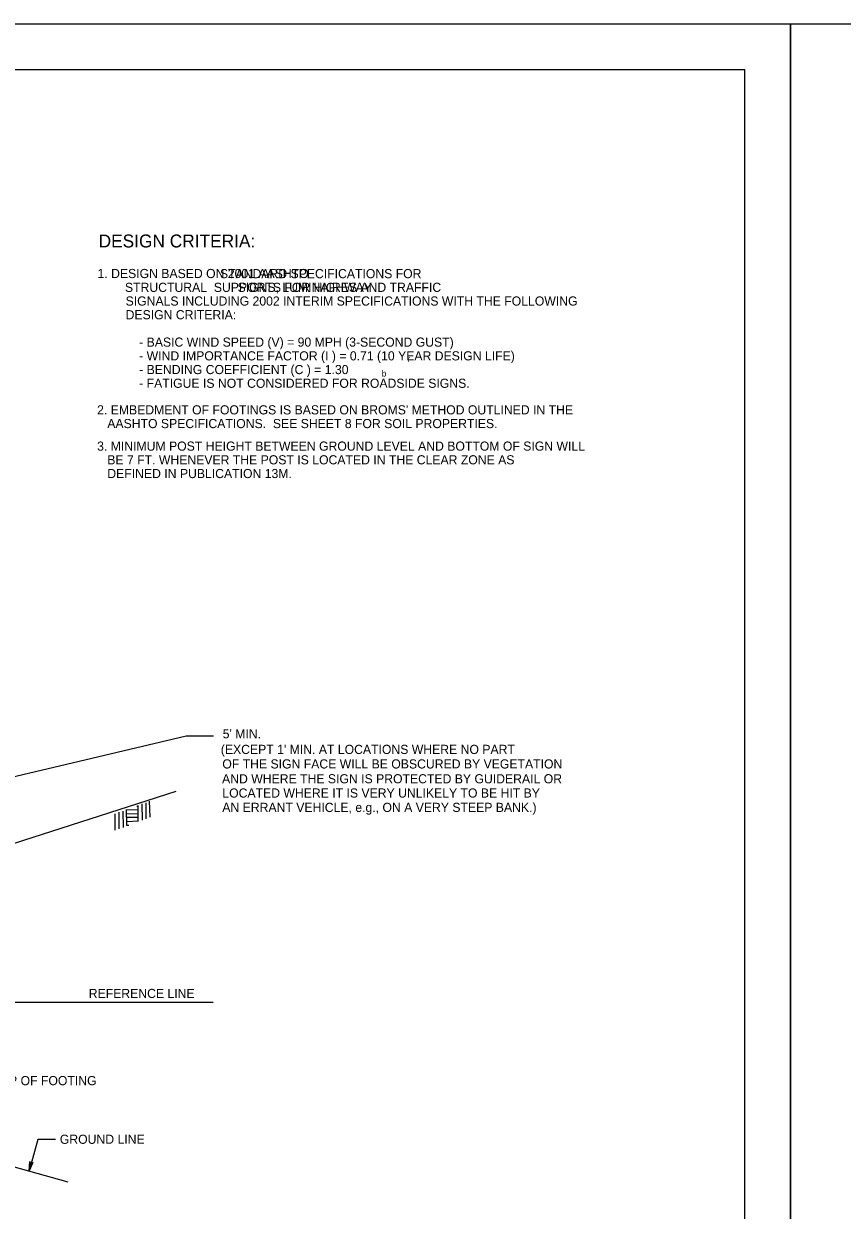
# Model space of a CAD drawing. Extents: x 637580 to 641008, y 294594 to 295782.
# Drawn here: x 638169.4 to 638438.3, y 295392.1 to 295781.6 of the extents above; entities that cross this region are included whole.
import ezdxf

# ---------------------------------------------------------------- set-up
doc = ezdxf.new("R2010")
doc.units = 0
for name, color, linetype in [('1', 7, 'Continuous'), ('2', 7, 'Continuous'), ('3', 7, 'Continuous'), ('PLT-BNDY', 7, 'Continuous')]:
    doc.layers.add(name, color=color, linetype=linetype)

# ---------------------------------------------------------------- blocks, each defined once
blk = doc.blocks.new('RARROW')
at = {"layer": '3'}
blk.add_lwpolyline([(-2.2695, 0.285), (-2.184875, 0.12075), (0, 0), (-2.2695, 0.285), (-2.38575, 0.384625), (0, 0), (-2.183125, -0.108), (-2.262875, -0.2705), (0, 0), (-2.38575, -0.379125), (-2.262875, -0.2705)], dxfattribs=at)

msp = doc.modelspace()

# ---------------------------------------------------------------- linework, layer by layer
at = {"layer": '1'}
for p, q in [((637620.31, 295766.63), (638406.31, 295766.63)), ((638406.31, 295202.63), (638406.31, 295766.63)), ((638148.69, 295530.25), (638222.81, 295547.88)), ((638210.94, 295521.13), (638210.81, 295526.38)), ((638199.44, 295516.88), (638199.44, 295522.25)), ((638200.81, 295517.25), (638200.81, 295522.75)), ((638202.19, 295517.75), (638202.06, 295523.13)), ((638203.19, 295523.5), (638207.06, 295523.63)), ((638203.31, 295518.38), (638203.19, 295523.63)), ((638203.31, 295522.25), (638207.19, 295522.38)), ((638206.56, 295524.75), (638207.06, 295524.75)), ((638207.06, 295519.75), (638207.06, 295525)), ((638208.44, 295520.13), (638208.31, 295525.5)), ((638209.69, 295520.63), (638209.69, 295525.88)), ((638203.31, 295521.13), (638207.06, 295521.13)), ((638203.31, 295519.75), (638207.19, 295519.88)), ((638203.31, 295518.5), (638203.94, 295518.5))]:
    msp.add_line(p, q, dxfattribs=at)
at = {"layer": '2'}
for p, q in [((638222.81, 295547.88), (638231.81, 295547.88)), ((638163.06, 295511.5), (638219.56, 295529.63)), ((637724.69, 295460.38), (638231.69, 295460.38)), ((637988.94, 295455.5), (638183.94, 295401.38)), ((638174.06, 295415.25), (638171.19, 295405)), ((638179.94, 295415.25), (638174.06, 295415.25))]:
    msp.add_line(p, q, dxfattribs=at)
at = {"layer": 'PLT-BNDY'}
for points in [[(637580.31, 295781.63), (638421.31, 295781.63), (638421.31, 295187.63), (637580.31, 295187.63)], [(638421.31, 295781.63), (639262.31, 295781.63), (639262.31, 295187.63), (638421.31, 295187.63)]]:
    msp.add_lwpolyline(points, close=True, dxfattribs=at)

# ---------------------------------------------------------------- block references
at = {"layer": '2', "xscale": 1.2574347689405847, "yscale": 1.3092961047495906, "rotation": -105.39526430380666}
msp.add_blockref('RARROW', (638171.19, 295405), dxfattribs=at)

# ---------------------------------------------------------------- texts
at = {"layer": '1'}
for s, height, p in [('1. DESIGN BASED ON 2001 AASHTO ', 3, (638193.69, 295698.12)), ('                            STANDARD SPECIFICATIONS FOR', 3, (638202.7, 295698.08)), ('STRUCTURAL  SUPPORTS FOR HIGHWAY ', 3, (638202.7, 295693.58)), ('                                 SIGNS, LUMINAIRES AND TRAFFIC', 3, (638202.92, 295693.59)), ('SIGNALS INCLUDING 2002 INTERIM SPECIFICATIONS WITH THE FOLLOWING', 3, (638202.92, 295689.09)), ('DESIGN CRITERIA:', 3, (638202.92, 295684.59)), ('    - BASIC WIND SPEED (V) = 90 MPH (3-SECOND GUST)', 3, (638202.92, 295675.59)), ('    - WIND IMPORTANCE FACTOR (I ) = 0.71 (10 YEAR DESIGN LIFE)', 3, (638202.92, 295671.09)), ('r', 2, (638295.45, 295670.57)), ('    - BENDING COEFFICIENT (C ) = 1.30', 3, (638202.92, 295666.59)), ('b', 2, (638287.06, 295665.79)), ('    - FATIGUE IS NOT CONSIDERED FOR ROADSIDE SIGNS.', 3, (638202.92, 295662.09)), ("2. EMBEDMENT OF FOOTINGS IS BASED ON BROMS' METHOD OUTLINED IN THE", 3, (638193.56, 295653.36)), ('   AASHTO SPECIFICATIONS.  SEE SHEET 8 FOR SOIL PROPERTIES.', 3, (638193.56, 295648.86)), ('3. MINIMUM POST HEIGHT BETWEEN GROUND LEVEL AND BOTTOM OF SIGN WILL', 3, (638193.56, 295641.45)), ('   BE 7 FT. WHENEVER THE POST IS LOCATED IN THE CLEAR ZONE AS', 3, (638193.56, 295636.95)), ('   DEFINED IN PUBLICATION 13M.', 3, (638193.56, 295632.45)), ("5' MIN.", 3, (638234.81, 295547)), ("(EXCEPT 1' MIN. AT LOCATIONS WHERE NO PART", 3, (638234.19, 295541.88)), ('OF THE SIGN FACE WILL BE OBSCURED BY VEGETATION', 3, (638234.69, 295537.11)), ('AND WHERE THE SIGN IS PROTECTED BY GUIDERAIL OR', 3, (638234.6, 295532.23)), ('LOCATED WHERE IT IS VERY UNLIKELY TO BE HIT BY', 3, (638234.69, 295527.56)), ('AN ERRANT VEHICLE, e.g., ON A VERY STEEP BANK.)', 3, (638234.68, 295522.84))]:
    msp.add_text(s, height=height, dxfattribs=at).set_placement(p)
at = {"layer": '2'}
msp.add_text('DESIGN CRITERIA:', height=4.25, dxfattribs=at).set_placement((638194.05, 295708.17))
at = {"layer": '3'}
for s, p in [('REFERENCE LINE', (638190.81, 295461.75)), ('TOP OF FOOTING', (638159.06, 295433.13)), ('GROUND LINE', (638181.31, 295413.88))]:
    msp.add_text(s, height=3, dxfattribs=at).set_placement(p)

doc.saveas('drawing.dxf')
